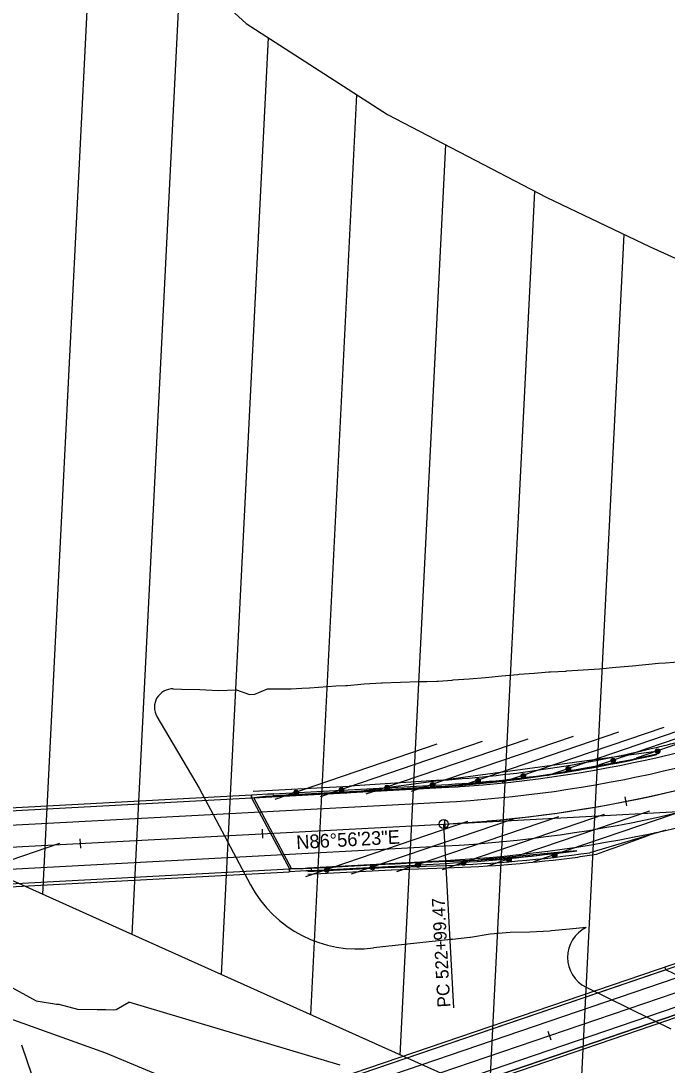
# Model space of a CAD drawing. Extents: x 1300404 to 1323571, y 237813 to 252077.
# Drawn here: x 1310687 to 1311041, y 241720 to 242293 of the extents above; entities that cross this region are included whole.
import ezdxf

# ---------------------------------------------------------------- set-up
doc = ezdxf.new("R2010")
doc.units = 0
for name, color, linetype in [('R_Bridge', 7, 'Continuous'), ('R_Const Limits', 7, 'Continuous'), ('R_Floodway', 7, 'Continuous'), ('R_Flooplain', 7, 'Continuous'), ('R_Guardrail', 7, 'Continuous'), ('R_Horz Alg Annot', 7, 'Continuous'), ('R_Horz Alg Annot Leader', 7, 'Continuous'), ('R_Horz Alg Minor Ticks', 7, 'Continuous'), ('R_Horz Alg Tangents', 7, 'Continuous'), ('R_Horz Alg Tangents Text', 7, 'Continuous'), ('R_Lane Edge', 7, 'Continuous'), ('R_No Plot', 7, 'Continuous'), ('R_Proposed', 7, 'Continuous'), ('R_Shoulder', 7, 'Continuous'), ('T_Drafting', 7, 'Continuous')]:
    doc.layers.add(name, color=color, linetype=linetype)

msp = doc.modelspace()

# ---------------------------------------------------------------- linework, layer by layer
at = {"layer": 'R_Bridge'}
for p, q in [((1310825.04, 241869.03), (1310813.06, 241868.37)), ((1310825.09, 241868.03), (1310825.04, 241869.03)), ((1310634.41, 241858.98), (1310813.05, 241868.54)), ((1310634.49, 241857.41), (1310813.13, 241866.96)), ((1310813.13, 241866.95), (1310813.05, 241868.52)), ((1310813.06, 241868.37), (1310813.13, 241866.97)), ((1310813.13, 241866.97), (1310820.6, 241867.78)), ((1310813.13, 241866.95), (1310833.89, 241828.01)), ((1310814.19, 241867.08), (1310834.99, 241828.07)), ((1310820.6, 241867.78), (1310825.09, 241868.03)), ((1310655.25, 241818.46), (1310833.89, 241828.01)), ((1310655.34, 241816.88), (1310833.98, 241826.43)), ((1310833.98, 241826.41), (1310833.89, 241828.01)), ((1310841.4, 241827.99), (1310833.89, 241828.01)), ((1310833.89, 241828.01), (1310833.97, 241826.59)), ((1310833.97, 241826.59), (1310845.95, 241827.23)), ((1310845.9, 241828.23), (1310841.4, 241827.99)), ((1310845.95, 241827.23), (1310845.9, 241828.23)), ((1311052, 241778.36), (1310793.35, 241690.31)), ((1311052.51, 241776.86), (1310793.86, 241688.82)), ((1311040.21, 241772.68), (1310793.86, 241688.82)), ((1311040.21, 241772.68), (1311039.7, 241774.17)), ((1311071.93, 241757.07), (1311040.21, 241772.68)), ((1311071.93, 241757.07), (1310825.58, 241673.21)), ((1311072.44, 241755.57), (1310826.09, 241671.71))]:
    msp.add_line(p, q, dxfattribs=at)
at = {"layer": 'R_Const Limits'}
for p, q in [((1310761.31, 241911.48), (1310784.4, 241872.17)), ((1310861.71, 241720.47), (1310745.98, 241755.04))]:
    msp.add_line(p, q, dxfattribs=at)
for points in [[(1310770.25, 241926.64), (1310774.78, 241926.52), (1310784.81, 241926.21), (1310794.84, 241925.8), (1310804.84, 241926.02), (1310812.1, 241923.63), (1310814.98, 241923.67), (1310821.96, 241926.57), (1310824.84, 241926.6), (1310825.84, 241926.61), (1310834.85, 241926.68), (1310840.61, 241926.98), (1310844.84, 241927.26), (1310854.81, 241927.93), (1310859.32, 241928.23), (1310864.8, 241928.45), (1310865.67, 241928.55), (1310874.76, 241929.47), (1310884.27, 241929.9), (1310884.75, 241929.92), (1310894.74, 241930.32), (1310904.74, 241930.67), (1310909.26, 241930.74), (1310914.69, 241930.86), (1310915.46, 241930.89), (1310923.14, 241931.46), (1310923.57, 241931.5), (1310932.44, 241932.19), (1310941.32, 241932.89), (1310950.19, 241933.75), (1310959.05, 241934.6), (1310959.83, 241934.67), (1310967.95, 241935.3), (1310976.02, 241935.92), (1310976.44, 241935.95), (1310976.87, 241935.98), (1310985.41, 241936.41), (1310985.84, 241936.44), (1310994.8, 241937.11), (1311003.81, 241937.66), (1311012.81, 241938.45), (1311015.07, 241938.66), (1311021.82, 241939.3), (1311027.12, 241939.83), (1311030.85, 241940.22), (1311036.15, 241940.81), (1311039.95, 241940.99), (1311049.13, 241941.61)], [(1310784.4, 241872.17), (1310812.56, 241819.34)], [(1310996.5, 241795.79), (1310987.43, 241794.97), (1310977.53, 241794.02), (1310976.58, 241793.94), (1310965.69, 241793.37), (1310954.78, 241793.17), (1310943.95, 241792.29), (1310933.19, 241790.4), (1310932.68, 241790.31), (1310923.31, 241789.31), (1310922.36, 241789.24), (1310880.01, 241784.67), (1310880.01, 241784.67)], [(1310628.59, 241717.21), (1310638.32, 241722.5), (1310645.83, 241733.71), (1310653.82, 241744.11), (1310654.75, 241745.22), (1310662.42, 241753.21), (1310672.3, 241758.99), (1310682.14, 241762.89), (1310695.17, 241755.66), (1310706.32, 241753.92), (1310707.57, 241753.78), (1310717.84, 241751.11), (1310728.47, 241750.91), (1310733.3, 241751.02), (1310737.75, 241750.82), (1310739.04, 241750.92), (1310745.98, 241755.04)], [(1310996.41, 241763.17), (1311042.87, 241740.4)]]:
    msp.add_lwpolyline(points, dxfattribs=at)
for centre, radius, start, end in [((1310769.99, 241916.58), 10.07, 88.5132, 210.4349), ((1310871.29, 241850.65), 66.55, 208.0604, 277.5275), ((1311004.39, 241779.46), 18.14, 115.7858, 243.8919)]:
    msp.add_arc(centre, radius, start, end, dxfattribs=at)
at = {"layer": 'R_Floodway'}
for p, q in [((1310698.75, 241814.05), (1310726.49, 242367.67)), ((1310747.71, 241792.01), (1310774.36, 242323.99)), ((1310796.67, 241770.01), (1310822.39, 242283.45)), ((1310845.63, 241748), (1310870.89, 242252.19)), ((1310894.59, 241726), (1310919.58, 242224.73)), ((1310943.55, 241703.99), (1310968.37, 242199.27)), ((1310992.51, 241681.98), (1311017.25, 242175.67))]:
    msp.add_line(p, q, dxfattribs=at)
for points in [[(1313830.5, 242013.29), (1313725.05, 241936.34), (1313624.18, 241854.31), (1313605.13, 241763.33), (1313491.24, 241614.21), (1313390.85, 241541.84), (1313238.35, 241394.67), (1313129.75, 241351.75), (1313002.33, 241319.46), (1312893.25, 241266.88), (1312749.18, 241191.87), (1312719.26, 241174.03), (1312375.34, 241167.16), (1311696.89, 241341.68), (1311497.53, 241419.47), (1311333.82, 241508.77), (1311059.08, 241652.06), (1310740.78, 241795.13), (1310453.25, 241924.55), (1310367.2, 241994.21), (1310267.81, 242111.73), (1309996.24, 242391.57), (1309869.69, 242546.75), (1309624.53, 242919.62)], [(1310379.63, 242680.75), (1310490.18, 242568.72), (1310548.96, 242534.3), (1310676.05, 242414.18), (1310731.56, 242362.99), (1310810.26, 242291.28), (1310887.62, 242241.41), (1310974.87, 242195.88), (1311031.59, 242168.82), (1311109.67, 242133.43), (1311173.76, 242108.43), (1311242.66, 242083.18), (1311339.33, 242032.34), (1311351.04, 242024.49), (1311431.54, 241940.59), (1311405.15, 241750.77), (1311416.02, 241677.63), (1311441.14, 241598.94), (1311547.83, 241506.46), (1311691.44, 241475.03), (1311836.73, 241477.39), (1311974.41, 241472.87)]]:
    msp.add_lwpolyline(points, dxfattribs=at)
at = {"layer": 'R_Flooplain'}
msp.add_lwpolyline([(1309009.78, 242685.04), (1309044.07, 242596.21), (1309055.9, 242542.38), (1309352.07, 242367.77), (1309503.16, 242292.41), (1309669.46, 242230.8), (1309815.49, 242150.85), (1309936.66, 242057.64), (1310419.39, 241839.75), (1310733.16, 241727.16), (1311043.67, 241597.79), (1311103.17, 241577.86), (1311152.77, 241553.58), (1311178, 241525.7), (1311328.48, 241486.66), (1311553.07, 241380.98), (1311870.34, 241289.99), (1312137.52, 241213.62)], dxfattribs=at)
at = {"layer": 'R_Guardrail'}
for p, q in [((1311024.15, 241888.93), (1311112.89, 241919.14)), ((1310975.23, 241879.22), (1311063.98, 241909.43)), ((1310999.74, 241883.77), (1311088.49, 241913.98)), ((1310950.54, 241875.44), (1311039.29, 241905.65)), ((1310850.91, 241867.72), (1310939.66, 241897.93)), ((1310875.95, 241869.04), (1310964.69, 241899.25)), ((1310900.87, 241870.52), (1310989.62, 241900.73)), ((1310925.7, 241872.8), (1311014.45, 241903.01)), ((1310826.05, 241866.28), (1310914.79, 241896.49)), ((1310865.42, 241869.75), (1311034.82, 241892.52)), ((1311036.38, 241891.45), (1311034.42, 241892.42)), ((1311011.98, 241886.29), (1311010.01, 241887.25)), ((1310987.47, 241881.74), (1310985.5, 241882.7)), ((1310937.94, 241875.32), (1310935.97, 241876.29)), ((1310962.78, 241877.96), (1310960.81, 241878.93)), ((1310821.65, 241869), (1310917.25, 241874.11)), ((1310821.73, 241867.41), (1310865.42, 241869.75)), ((1310866.78, 241870.26), (1310825.09, 241868.03)), ((1310838.28, 241868.8), (1310836.32, 241869.77)), ((1310863.15, 241870.24), (1310861.18, 241871.21)), ((1310917.47, 241873.14), (1310866.78, 241870.26)), ((1310888.19, 241871.56), (1310886.22, 241872.53)), ((1310913.11, 241873.04), (1310911.14, 241874.01)), ((1310917.73, 241827.72), (1311006.48, 241857.93)), ((1310942.68, 241829.65), (1311031.43, 241859.86)), ((1310967.72, 241832.02), (1311056.47, 241862.23)), ((1310842.84, 241823.87), (1310931.58, 241854.08)), ((1310867.87, 241825.26), (1310956.61, 241855.47)), ((1310892.79, 241826.52), (1310981.54, 241856.73)), ((1310619.4, 241811.84), (1310708.15, 241842.05)), ((1310979.96, 241834.54), (1310977.99, 241835.51)), ((1310842.49, 241828.47), (1310886.18, 241830.8)), ((1310842.58, 241826.89), (1310919.55, 241831)), ((1310889.58, 241830.57), (1310845.9, 241828.23)), ((1310880.1, 241827.78), (1310878.14, 241828.75)), ((1310886.18, 241830.8), (1310919.47, 241832.58)), ((1310919.51, 241832), (1310889.6, 241830.57)), ((1310905.03, 241829.04), (1310903.06, 241830)), ((1310929.97, 241830.25), (1310928, 241831.21)), ((1310954.92, 241832.17), (1310952.95, 241833.14)), ((1310855.07, 241826.39), (1310853.11, 241827.36))]:
    msp.add_line(p, q, dxfattribs=at)
for points in [[(1311036.73, 241891.83), (1311034.51, 241892.92)], [(1311035.67, 241891.21), (1311034.66, 241891.71)], [(1311036.89, 241892.31), (1311034.79, 241893.34)], [(1311036.85, 241892.87), (1311035.26, 241893.66)], [(1310986.89, 241881.64), (1311011.49, 241886.09)], [(1311012.33, 241886.67), (1311010.1, 241887.76)], [(1311011.27, 241886.04), (1311010.25, 241886.54)], [(1311012.48, 241887.14), (1311010.39, 241888.17)], [(1311012.44, 241887.71), (1311010.86, 241888.49)], [(1311011.49, 241886.09), (1311021.72, 241887.94), (1311023.77, 241888.41)], [(1311023.77, 241888.41), (1311035.95, 241891.24)], [(1311035.95, 241891.24), (1311036.51, 241891.37)], [(1310974.59, 241879.41), (1310986.89, 241881.64)], [(1310987.81, 241882.12), (1310985.59, 241883.21)], [(1310986.76, 241881.49), (1310985.74, 241881.99)], [(1310987.97, 241882.59), (1310985.88, 241883.62)], [(1310987.93, 241883.16), (1310986.35, 241883.94)], [(1310913.45, 241873.43), (1310911.23, 241874.52)], [(1310913.61, 241873.9), (1310911.51, 241874.93)], [(1310913.57, 241874.47), (1310911.99, 241875.25)], [(1310924.91, 241873.91), (1310937.34, 241875.19)], [(1310938.28, 241875.7), (1310936.06, 241876.79)], [(1310937.23, 241875.08), (1310936.21, 241875.58)], [(1310938.44, 241876.18), (1310936.35, 241877.21)], [(1310938.4, 241876.74), (1310936.82, 241877.53)], [(1310937.34, 241875.19), (1310962.21, 241877.76)], [(1310963.13, 241878.35), (1310960.9, 241879.44)], [(1310962.07, 241877.72), (1310961.06, 241878.22)], [(1310963.28, 241878.82), (1310961.19, 241879.85)], [(1310963.25, 241879.39), (1310961.66, 241880.17)], [(1310962.21, 241877.76), (1310969.88, 241878.56), (1310974.59, 241879.41)], [(1310838.63, 241869.18), (1310836.41, 241870.28)], [(1310837.57, 241868.56), (1310836.56, 241869.06)], [(1310838.78, 241869.66), (1310836.69, 241870.69)], [(1310838.75, 241870.23), (1310837.16, 241871.01)], [(1310837.57, 241868.7), (1310862.54, 241870.03)], [(1310863.5, 241870.63), (1310861.28, 241871.72)], [(1310862.44, 241870), (1310861.43, 241870.5)], [(1310863.65, 241871.1), (1310861.56, 241872.13)], [(1310863.62, 241871.67), (1310862.03, 241872.45)], [(1310862.54, 241870.03), (1310866.78, 241870.26), (1310875.02, 241870.73)], [(1310875.02, 241870.73), (1310887.5, 241871.44)], [(1310888.53, 241871.95), (1310886.31, 241873.04)], [(1310887.48, 241871.32), (1310886.46, 241871.82)], [(1310888.69, 241872.42), (1310886.59, 241873.45)], [(1310888.65, 241872.99), (1310887.06, 241873.77)], [(1310887.5, 241871.44), (1310912.46, 241872.85)], [(1310912.4, 241872.8), (1310911.38, 241873.3)], [(1310912.46, 241872.85), (1310917.47, 241873.14), (1310924.91, 241873.91)], [(1310825.09, 241868.03), (1310837.57, 241868.7)], [(1310978.99, 241836.78), (1310954.11, 241834.41)], [(1310980.3, 241834.92), (1310978.08, 241836.02)], [(1310979.25, 241834.3), (1310978.23, 241834.8)], [(1310980.46, 241835.4), (1310978.36, 241836.43)], [(1310980.42, 241835.97), (1310978.84, 241836.75)], [(1310991.44, 241837.97), (1310978.99, 241836.78)], [(1310879.25, 241830.01), (1310854.28, 241828.68)], [(1310880.45, 241828.16), (1310878.23, 241829.26)], [(1310880.61, 241828.64), (1310878.51, 241829.67)], [(1310880.57, 241829.21), (1310878.98, 241829.99)], [(1310891.73, 241830.67), (1310889.6, 241830.57), (1310889.58, 241830.57), (1310879.25, 241830.01)], [(1310904.22, 241831.27), (1310891.73, 241830.67)], [(1310905.37, 241829.42), (1310903.15, 241830.51)], [(1310904.32, 241828.79), (1310903.3, 241829.29)], [(1310905.53, 241829.89), (1310903.44, 241830.92)], [(1310905.49, 241830.46), (1310903.91, 241831.24)], [(1310929.19, 241832.44), (1310919.51, 241832), (1310904.22, 241831.27)], [(1310930.32, 241830.63), (1310928.09, 241831.72)], [(1310929.26, 241830), (1310928.24, 241830.5)], [(1310930.47, 241831.1), (1310928.38, 241832.13)], [(1310930.43, 241831.67), (1310928.85, 241832.45)], [(1310941.66, 241833.23), (1310937.35, 241832.82), (1310929.19, 241832.44)], [(1310954.11, 241834.41), (1310941.66, 241833.23)], [(1310955.27, 241832.55), (1310953.05, 241833.64)], [(1310954.21, 241831.93), (1310953.2, 241832.43)], [(1310955.42, 241833.03), (1310953.33, 241834.06)], [(1310955.39, 241833.59), (1310953.8, 241834.38)], [(1310854.28, 241828.68), (1310845.9, 241828.23)], [(1310855.42, 241826.77), (1310853.2, 241827.87)], [(1310854.37, 241826.15), (1310853.35, 241826.65)], [(1310855.58, 241827.25), (1310853.48, 241828.28)], [(1310855.54, 241827.82), (1310853.95, 241828.6)], [(1310879.4, 241827.54), (1310878.38, 241828.04)]]:
    msp.add_lwpolyline(points, dxfattribs=at)
for centre in [(1311035.67, 241892.47), (1311011.26, 241887.31), (1310962.06, 241878.99), (1310986.75, 241882.76), (1310912.39, 241874.07), (1310937.22, 241876.34), (1310837.57, 241869.83), (1310862.43, 241871.27), (1310887.47, 241872.59), (1310954.2, 241833.19), (1310979.24, 241835.56), (1310879.39, 241828.8), (1310904.31, 241830.06), (1310929.25, 241831.27), (1310854.36, 241827.42)]:
    msp.add_circle(centre, 1.25, dxfattribs=at)
for centre, radius, start, end in [((1310880.16, 242567.73), 694.62, 273.06037, 282.9012), ((1310872.29, 242565.86), 694.2, 273.73154, 283.68361), ((1310894.5, 242569.77), 738.2, 271.9418, 277.54588), ((1310880.16, 242567.73), 737.78, 273.06037, 278.39407)]:
    msp.add_arc(centre, radius, start, end, dxfattribs=at)
at = {"layer": 'R_Horz Alg Annot Leader'}
for points in [[(1310918.4, 241852.55), (1310923.78, 241751.89)], [(1310687.13, 241731.51), (1310715.59, 241647.91)]]:
    msp.add_lwpolyline(points, dxfattribs=at)
at = {"layer": 'R_Horz Alg Minor Ticks'}
for points in [[(1311017.6, 241867.39), (1311018.56, 241862.48)], [(1310918.79, 241855.08), (1310919.06, 241850.09)], [(1310818.94, 241849.74), (1310819.2, 241844.75)], [(1310719.08, 241844.4), (1310719.35, 241839.41)], [(1310975.48, 241739.02), (1310977.09, 241734.29)]]:
    msp.add_lwpolyline(points, dxfattribs=at)
at = {"layer": 'R_Horz Alg Tangents'}
msp.add_line((1310918.4, 241852.55), (1311176.79, 241866.37), dxfattribs=at)
at = {"layer": 'R_Lane Edge'}
for p, q in [((1310713.17, 241655.01), (1311572.42, 241947.51)), ((1310718.01, 241640.81), (1311577.25, 241933.31)), ((1310472.71, 241840.74), (1310917.76, 241864.54)), ((1310551.65, 241820.93), (1310919.04, 241840.57))]:
    msp.add_line(p, q, dxfattribs=at)
for radius in [704.2, 728.2]:
    msp.add_arc((1310880.16, 242567.73), radius, 273.06037, 312.78965, dxfattribs=at)
at = {"layer": 'R_No Plot'}
for p, q in [((1311040.18, 241849.13), (1310998.46, 241836.84)), ((1310843.98, 241826.54), (1310886.27, 241828.8)), ((1310886.27, 241828.8), (1310919.57, 241829.92))]:
    msp.add_line(p, q, dxfattribs=at)
msp.add_arc((1310894.44, 242568.89), 739.4, 271.94765, 278.08737, dxfattribs=at)
at = {"layer": 'R_Proposed'}
for p, q in [((1310715.59, 241647.91), (1311574.84, 241940.41)), ((1310473.35, 241828.76), (1310918.4, 241852.55))]:
    msp.add_line(p, q, dxfattribs=at)
msp.add_circle((1310918.4, 241852.55), 2.5, dxfattribs=at)
for start in [273.06037, 273.06037, 274.98457, 274.98457]:
    msp.add_arc((1310880.16, 242567.73), 716.2, start, 312.78965, dxfattribs=at)
at = {"layer": 'R_Shoulder'}
for p, q in [((1310766.63, 241653.14), (1311578.54, 241929.52)), ((1310917.24, 241876.63), (1310866.75, 241873.34)), ((1310814.05, 241870.51), (1310866.62, 241873.32)), ((1310814.23, 241867.01), (1310917.33, 241872.53)), ((1310814.23, 241867.01), (1310866.8, 241869.82)), ((1310843.88, 241828.54), (1310919.47, 241832.58)), ((1310844.06, 241825.05), (1310889.75, 241827.49)), ((1310889.7, 241827.49), (1310919.63, 241828.5))]:
    msp.add_line(p, q, dxfattribs=at)
for centre, radius, start, end in [((1310880.16, 242567.73), 696.2, 273.06037, 312.78965), ((1310880.16, 242567.73), 736.2, 273.06037, 312.78965), ((1310872.29, 242565.86), 690.7, 273.73154, 283.68361), ((1310880.16, 242567.73), 690.7, 283.01244, 283.81244), ((1310762.89, 242545.39), 748.52, 288.63889, 291.27888), ((1310894.5, 242569.77), 741.7, 271.9418, 277.54588), ((1310880.16, 242567.73), 741.7, 278.66444, 279.46444)]:
    msp.add_arc(centre, radius, start, end, dxfattribs=at)
at = {"layer": 'T_Drafting'}
msp.add_line((1310473.35, 241828.76), (1310918.4, 241852.55), dxfattribs=at)

# ---------------------------------------------------------------- texts
at = {"layer": 'R_Horz Alg Annot'}
msp.add_text('PC 522+99.47', height=7, rotation=93.0604, dxfattribs=at).set_placement((1310922.09, 241752.27))
at = {"layer": 'R_Horz Alg Tangents Text'}
msp.add_text('N86%%d56\'23"E', height=7.5, rotation=3.0604, dxfattribs=at).set_placement((1310837.82, 241838.83))

doc.saveas('drawing.dxf')
